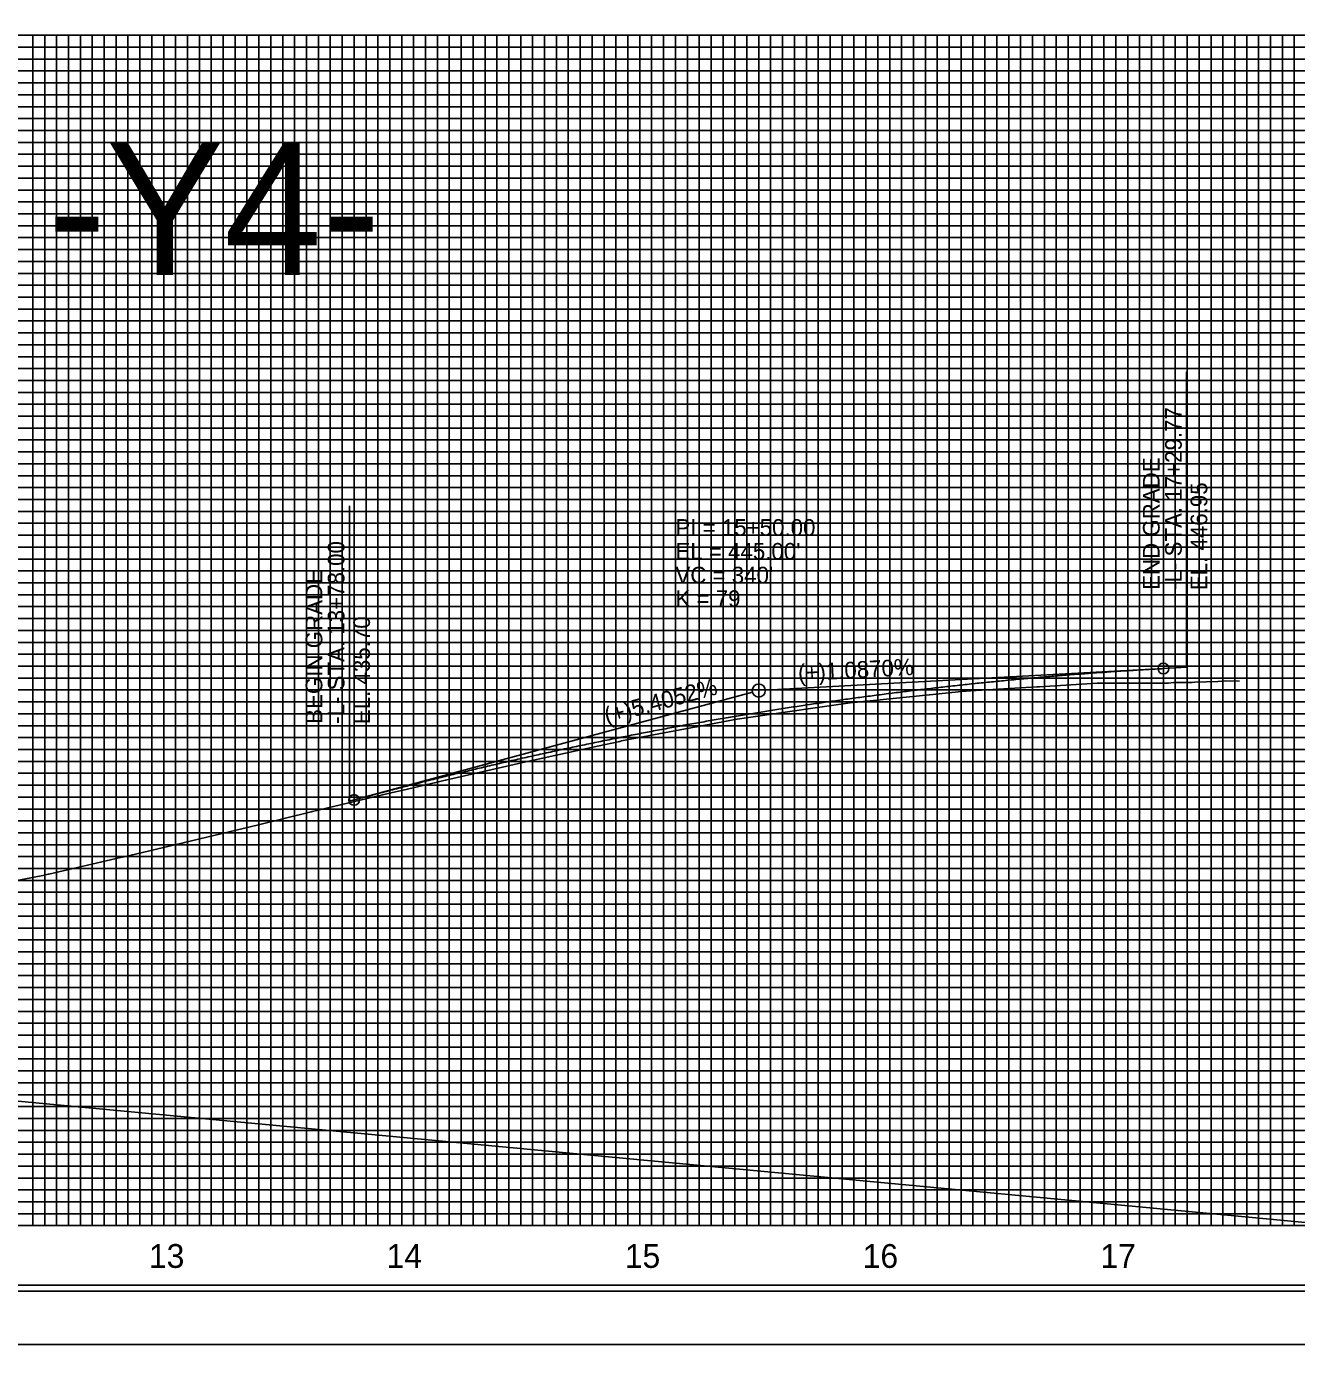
# Model space of a CAD drawing. Extents: x 571503 to 593215, y -77195 to -51828.
# Drawn here: x 586818 to 587352, y -53731 to -53168 of the extents above; entities that cross this region are included whole.
import ezdxf

# ---------------------------------------------------------------- set-up
doc = ezdxf.new("R2010")
doc.units = 0
for name, color, linetype in [('Default', 7, 'Continuous'), ('Exist Vertical Profile Ground Line', 7, 'Continuous'), ('Exist Vertical Profile Horizontal Axis Label Major', 7, 'Continuous'), ('Prop PFL Text', 7, 'Continuous'), ('Prop Vertical Profile Curve Label', 7, 'Continuous'), ('Prop Vertical Profile Grade', 7, 'Continuous'), ('Prop Vertical Profile Grade Label', 7, 'Continuous'), ('Prop VPI Label', 7, 'Continuous'), ('Sheet Clip Boundary CELL', 7, 'Continuous'), ('Sheet DOT Grid CELL', 7, 'Continuous'), ('Sheet Plot Border Inside CELL', 7, 'Continuous'), ('Sheet Plot Border Outside CELL', 7, 'Continuous'), ('Sheet Profile CELL', 7, 'Continuous'), ('Sheet Profile Grid Major CELL', 7, 'Continuous'), ('Sheet Profile Grid Middle CELL', 7, 'Continuous'), ('Sheet Profile Grid Minor CELL', 7, 'Continuous')]:
    doc.layers.add(name, color=color, linetype=linetype)

msp = doc.modelspace()

# ---------------------------------------------------------------- linework, layer by layer
at = {"layer": 'Exist Vertical Profile Ground Line'}
msp.add_lwpolyline([(586805.4, -53527.81), (586825.12, -53523.99), (586827.43, -53523.54), (586827.74, -53523.47), (586857.78, -53516.5), (586859.3, -53516.15), (586883.55, -53510.52), (586883.76, -53510.47), (586884.7, -53510.25), (586915.74, -53502.7), (586937.93, -53497.31), (586938.31, -53497.22), (586938.45, -53497.19), (586970.17, -53489.65), (586970.24, -53489.64), (586978.3, -53487.72), (586990.78, -53484.78), (586994.25, -53483.98), (586994.39, -53483.95), (587026.19, -53476.68), (587026.79, -53476.55), (587058.13, -53469.76), (587058.17, -53469.75), (587067.52, -53467.72), (587068.24, -53467.55), (587099.6, -53461.65), (587099.81, -53461.62), (587116.66, -53458.44), (587116.9, -53458.4), (587148.58, -53453.83), (587148.7, -53453.81), (587165.35, -53451.41), (587165.91, -53451.33), (587197.5, -53448.14), (587197.66, -53448.12), (587211.08, -53446.77), (587211.25, -53446.75), (587215.05, -53446.5), (587242.81, -53444.87), (587242.83, -53444.87), (587243.88, -53444.75), (587268.09, -53443.28), (587269, -53443.25), (587298.02, -53443.2), (587300.11, -53443.05), (587305.77, -53442.93), (587306.85, -53442.92), (587306.97, -53442.98), (587308.03, -53442.94), (587308.97, -53442.9), (587318.8, -53442.57), (587322.21, -53442.33), (587327.89, -53442.44)], dxfattribs=at)
at = {"layer": 'Prop PFL Text'}
msp.add_line((571620.66, -52186.29), (592499.52, -54154.87), dxfattribs=at)
at = {"layer": 'Prop Vertical Profile Curve Label'}
for centre in [(587295.93, -53437.13), (586955.93, -53492.32)]:
    msp.add_circle(centre, 2.25, dxfattribs=at)
at = {"layer": 'Prop Vertical Profile Grade'}
for p, q in [((587295.93, -53437.13), (587305.7, -53436.6)), ((586953.93, -53492.86), (586955.93, -53492.32))]:
    msp.add_line(p, q, dxfattribs=at)
msp.add_spline([(586955.93, -53492.32), (586962.73, -53490.49), (586969.53, -53488.7), (586976.33, -53486.94), (586983.13, -53485.2), (586989.93, -53483.5), (586996.73, -53481.82), (587003.53, -53480.17), (587010.33, -53478.56), (587017.13, -53476.97), (587023.93, -53475.41), (587030.73, -53473.88), (587037.53, -53472.38), (587044.33, -53470.91), (587051.13, -53469.47), (587057.93, -53468.05), (587064.73, -53466.67), (587071.53, -53465.32), (587078.33, -53463.99), (587085.13, -53462.7), (587091.93, -53461.44), (587098.73, -53460.2), (587105.53, -53458.99), (587112.33, -53457.82), (587119.13, -53456.67), (587125.93, -53455.55), (587132.73, -53454.46), (587139.53, -53453.4), (587146.33, -53452.37), (587153.13, -53451.37), (587159.93, -53450.4), (587166.73, -53449.46), (587173.53, -53448.54), (587180.33, -53447.66), (587187.13, -53446.81), (587193.93, -53445.98), (587200.73, -53445.19), (587207.53, -53444.42), (587214.33, -53443.68), (587221.13, -53442.98), (587227.93, -53442.3), (587234.73, -53441.65), (587241.53, -53441.03), (587248.33, -53440.44), (587255.13, -53439.88), (587261.93, -53439.35), (587268.73, -53438.85), (587275.53, -53438.37), (587282.33, -53437.93), (587289.13, -53437.52), (587295.93, -53437.13)], degree=3, dxfattribs=at)
at = {"layer": 'Prop VPI Label'}
for p, q in [((587305.7, -53436.6), (587305.7, -53312.47)), ((586953.93, -53492.86), (586953.93, -53368.73)), ((587295.93, -53437.13), (587128.68, -53446.22)), ((586955.93, -53492.32), (587123.28, -53447.09))]:
    msp.add_line(p, q, dxfattribs=at)
msp.add_circle((587125.93, -53446.37), 2.75, dxfattribs=at)
at = {"layer": 'Sheet Clip Boundary CELL'}
msp.add_lwpolyline([(585975.93, -53171.12), (587375.93, -53171.12), (587375.93, -53671.12), (585975.93, -53671.12)], close=True, dxfattribs=at)
at = {"layer": 'Sheet DOT Grid CELL'}
for p, q in [((585925.93, -53171.12), (587425.82, -53171.12)), ((586825.93, -53671.12), (586825.93, -53171.12)), ((586825.93, -53171.12), (586825.93, -53671.12)), ((586875.93, -53671.12), (586875.93, -53171.12)), ((586875.93, -53171.12), (586875.93, -53671.12)), ((586925.93, -53671.12), (586925.93, -53171.12)), ((586925.93, -53171.12), (586925.93, -53671.12)), ((586975.93, -53671.12), (586975.93, -53171.12)), ((586975.93, -53171.12), (586975.93, -53671.12)), ((587025.93, -53671.12), (587025.93, -53171.12)), ((587025.93, -53171.12), (587025.93, -53671.12)), ((587075.93, -53671.12), (587075.93, -53171.12)), ((587075.93, -53171.12), (587075.93, -53671.12)), ((587125.93, -53671.12), (587125.93, -53171.12)), ((587125.93, -53171.12), (587125.93, -53671.12)), ((587175.93, -53671.12), (587175.93, -53171.12)), ((587175.93, -53171.12), (587175.93, -53671.12)), ((587225.93, -53671.12), (587225.93, -53171.12)), ((587225.93, -53171.12), (587225.93, -53671.12)), ((587275.93, -53671.12), (587275.93, -53171.12)), ((587275.93, -53171.12), (587275.93, -53671.12)), ((587325.93, -53671.12), (587325.93, -53171.12)), ((587325.93, -53171.12), (587325.93, -53671.12)), ((585925.93, -53221.12), (587425.93, -53221.12)), ((585925.93, -53221.12), (587425.82, -53221.12)), ((585925.93, -53271.12), (587425.93, -53271.12)), ((585925.93, -53271.12), (587425.82, -53271.12)), ((585925.93, -53321.12), (587425.93, -53321.12)), ((585925.93, -53321.12), (587425.82, -53321.12)), ((585925.93, -53371.12), (587425.93, -53371.12)), ((585925.93, -53371.12), (587425.82, -53371.12)), ((585925.93, -53421.12), (587425.93, -53421.12)), ((585925.93, -53421.12), (587425.82, -53421.12)), ((585925.93, -53471.12), (587425.93, -53471.12)), ((585925.93, -53471.12), (587425.82, -53471.12)), ((585925.93, -53521.12), (587425.82, -53521.12)), ((585925.93, -53571.12), (587425.82, -53571.12)), ((586575.93, -53571.12), (587425.93, -53571.12)), ((585925.93, -53621.12), (587425.93, -53621.12)), ((585925.93, -53621.12), (587425.82, -53621.12))]:
    msp.add_line(p, q, dxfattribs=at)
at = {"layer": 'Sheet Plot Border Inside CELL'}
msp.add_lwpolyline([(585771.93, -53698.67), (587438.43, -53698.67), (587438.43, -52643.57), (585771.93, -52643.57)], close=True, dxfattribs=at)
at = {"layer": 'Sheet Plot Border Outside CELL'}
msp.add_lwpolyline([(585758.93, -53721.12), (587442.93, -53721.12), (587442.93, -52621.12), (585758.93, -52621.12)], close=True, dxfattribs=at)
at = {"layer": 'Sheet Profile CELL'}
for p, q in [((585925.93, -53171.12), (587425.93, -53171.12)), ((587425.93, -53671.12), (585925.93, -53671.12)), ((585925.93, -53696.12), (587425.93, -53696.12)), ((585758.93, -53721.12), (587442.93, -53721.12))]:
    msp.add_line(p, q, dxfattribs=at)
msp.add_lwpolyline([(587425.93, -52646.12), (585925.93, -52646.12), (585925.93, -53696.12), (587425.93, -53696.12)], close=True, dxfattribs=at)
at = {"layer": 'Sheet Profile Grid Major CELL'}
for p, q in [((586825.93, -53171.12), (586875.93, -53171.12)), ((586925.93, -53171.12), (586975.93, -53171.12)), ((587025.93, -53171.12), (587075.93, -53171.12)), ((587125.93, -53171.12), (587175.93, -53171.12)), ((587225.93, -53171.12), (587275.93, -53171.12)), ((587325.93, -53171.12), (587375.93, -53171.12)), ((587325.93, -53671.12), (587325.93, -53671.12))]:
    msp.add_line(p, q, dxfattribs=at)
for points in [[(586775.93, -53671.12), (586825.93, -53671.12), (586825.93, -53171.12), (586875.93, -53171.12), (586875.93, -53671.12), (586925.93, -53671.12), (586925.93, -53171.12), (586975.93, -53171.12), (586975.93, -53671.12), (587025.93, -53671.12), (587025.93, -53171.12), (587075.93, -53171.12), (587075.93, -53671.12), (587125.93, -53671.12), (587125.93, -53171.12), (587175.93, -53171.12), (587175.93, -53671.12), (587225.93, -53671.12), (587225.93, -53171.12), (587275.93, -53171.12), (587275.93, -53671.12), (587325.93, -53671.12), (587325.93, -53671.12), (587325.93, -53171.12), (587375.93, -53171.12)], [(587425.93, -53221.12), (585925.93, -53221.12)], [(587425.93, -53271.12), (585925.93, -53271.12), (585925.93, -53321.12), (587425.93, -53321.12)], [(587425.93, -53371.12), (585925.93, -53371.12), (585925.93, -53421.12), (587425.93, -53421.12)], [(587425.93, -53471.12), (585925.93, -53471.12), (585925.93, -53521.12), (587425.93, -53521.12)], [(587425.93, -53571.12), (585925.93, -53571.12), (585925.93, -53571.12), (585925.93, -53621.12), (587425.93, -53621.12)], [(587425.93, -53671.12), (585925.93, -53671.12)]]:
    msp.add_lwpolyline(points, dxfattribs=at)
at = {"layer": 'Sheet Profile Grid Middle CELL'}
for p, q in [((586850.93, -53671.12), (586850.93, -53171.12)), ((586850.93, -53171.12), (586900.93, -53171.12)), ((586900.93, -53171.12), (586900.93, -53671.12)), ((586950.93, -53671.12), (586950.93, -53171.12)), ((586950.93, -53171.12), (587000.93, -53171.12)), ((587000.93, -53171.12), (587000.93, -53671.12)), ((587050.93, -53671.12), (587050.93, -53171.12)), ((587050.93, -53171.12), (587100.93, -53171.12)), ((587100.93, -53171.12), (587100.93, -53671.12)), ((587150.93, -53671.12), (587150.93, -53171.12)), ((587150.93, -53171.12), (587200.93, -53171.12)), ((587200.93, -53171.12), (587200.93, -53671.12)), ((587250.93, -53671.12), (587250.93, -53171.12)), ((587250.93, -53171.12), (587300.93, -53171.12)), ((587300.93, -53171.12), (587300.93, -53671.12)), ((587350.93, -53671.12), (587350.93, -53171.12)), ((586800.93, -53671.12), (586850.93, -53671.12)), ((586900.93, -53671.12), (586950.93, -53671.12)), ((587000.93, -53671.12), (587050.93, -53671.12)), ((587100.93, -53671.12), (587150.93, -53671.12)), ((587200.93, -53671.12), (587250.93, -53671.12)), ((587300.93, -53671.12), (587350.93, -53671.12))]:
    msp.add_line(p, q, dxfattribs=at)
for points in [[(585925.93, -53196.12), (587425.93, -53196.12)], [(587375.93, -53246.12), (585925.93, -53246.12), (585925.93, -53296.12), (587425.93, -53296.12)], [(587425.93, -53346.12), (585925.93, -53346.12), (585925.93, -53396.12), (587425.93, -53396.12)], [(587425.93, -53446.12), (585925.93, -53446.12), (585925.93, -53496.12), (587425.93, -53496.12)], [(587425.93, -53546.12), (585925.93, -53546.12), (585925.93, -53596.12), (587425.93, -53596.12)], [(587425.93, -53646.12), (585925.93, -53646.12)]]:
    msp.add_lwpolyline(points, dxfattribs=at)
at = {"layer": 'Sheet Profile Grid Minor CELL'}
for p, q in [((586575.93, -53176.12), (587375.93, -53176.12)), ((587375.93, -53181.12), (586575.93, -53181.12)), ((586575.93, -53186.12), (587375.93, -53186.12)), ((587375.93, -53191.12), (586575.93, -53191.12)), ((586575.93, -53201.12), (587375.93, -53201.12)), ((587375.93, -53206.12), (586575.93, -53206.12)), ((586575.93, -53211.12), (587375.93, -53211.12)), ((587375.93, -53216.12), (586575.93, -53216.12)), ((586575.93, -53226.12), (587375.93, -53226.12)), ((587375.93, -53231.12), (586575.93, -53231.12)), ((586575.93, -53236.12), (587375.93, -53236.12)), ((587375.93, -53241.12), (586575.93, -53241.12)), ((586575.93, -53251.12), (587375.93, -53251.12)), ((587375.93, -53256.12), (586575.93, -53256.12)), ((586575.93, -53261.12), (587375.93, -53261.12)), ((587375.93, -53266.12), (586575.93, -53266.12)), ((586575.93, -53276.12), (587375.93, -53276.12)), ((587375.93, -53281.12), (586575.93, -53281.12)), ((586575.93, -53286.12), (587375.93, -53286.12)), ((587375.93, -53291.12), (586575.93, -53291.12)), ((586575.93, -53301.12), (587375.93, -53301.12)), ((587375.93, -53306.12), (586575.93, -53306.12)), ((586575.93, -53311.12), (587375.93, -53311.12)), ((587375.93, -53316.12), (586575.93, -53316.12)), ((586575.93, -53326.12), (587375.93, -53326.12)), ((587375.93, -53331.12), (586575.93, -53331.12)), ((586575.93, -53336.12), (587375.93, -53336.12)), ((587375.93, -53341.12), (586575.93, -53341.12)), ((586575.93, -53351.12), (587375.93, -53351.12)), ((587375.93, -53356.12), (586575.93, -53356.12)), ((586575.93, -53361.12), (587375.93, -53361.12)), ((587375.93, -53366.12), (586575.93, -53366.04)), ((586575.93, -53376.12), (587375.93, -53376.12)), ((587375.93, -53381.12), (586575.93, -53381.12)), ((586575.93, -53386.12), (587375.93, -53386.12)), ((587375.93, -53391.12), (586575.93, -53391.12)), ((586575.93, -53401.12), (587375.93, -53401.12)), ((587375.93, -53406.12), (586575.93, -53406.12)), ((586575.93, -53411.12), (587375.93, -53411.12)), ((587375.93, -53416.12), (586575.93, -53416.12)), ((586575.93, -53426.12), (587375.93, -53426.12)), ((587375.93, -53431.12), (586575.93, -53431.12)), ((586575.93, -53436.12), (587375.93, -53436.12)), ((587375.93, -53441.12), (586575.93, -53441.12)), ((586575.93, -53451.12), (587375.93, -53451.12)), ((587375.93, -53456.12), (586575.93, -53456.12)), ((586575.93, -53461.12), (587375.93, -53461.12)), ((587375.93, -53466.12), (586575.93, -53466.12)), ((586575.93, -53476.12), (587375.93, -53476.12)), ((587375.93, -53481.12), (586575.93, -53481.12)), ((586575.93, -53486.12), (587375.93, -53486.12)), ((587375.93, -53491.12), (586575.93, -53491.12)), ((586575.93, -53501.12), (587375.93, -53501.12)), ((587375.93, -53506.12), (586575.93, -53506.12)), ((586575.93, -53511.12), (587375.93, -53511.12)), ((587375.93, -53516.12), (586575.93, -53516.12)), ((586575.93, -53526.12), (587375.93, -53526.12)), ((587375.93, -53531.12), (586575.93, -53531.12)), ((586575.93, -53536.12), (587375.93, -53536.12)), ((587375.93, -53541.12), (586575.93, -53541.12)), ((586575.93, -53551.12), (587375.93, -53551.12)), ((587375.93, -53556.12), (586575.93, -53556.12)), ((586575.93, -53561.12), (587375.93, -53561.12)), ((587375.93, -53566.12), (586575.93, -53566.12)), ((586575.93, -53576.12), (587375.93, -53576.12)), ((587375.93, -53581.12), (586575.93, -53581.12)), ((586575.93, -53586.12), (587375.93, -53586.12)), ((587375.93, -53591.12), (586575.93, -53591.12)), ((586575.93, -53601.12), (587375.93, -53601.12)), ((587375.93, -53606.12), (586575.93, -53606.12)), ((586575.93, -53611.12), (587375.93, -53611.12)), ((587375.93, -53616.12), (586575.93, -53616.12)), ((586575.93, -53626.12), (587375.93, -53626.12)), ((587375.93, -53631.12), (586575.93, -53631.12)), ((586575.93, -53636.12), (587375.93, -53636.12)), ((587375.93, -53641.12), (586575.93, -53641.12)), ((586575.93, -53651.12), (587375.93, -53651.12)), ((587375.93, -53656.12), (586575.93, -53656.12)), ((586575.93, -53661.12), (587375.93, -53661.12)), ((586575.93, -53666.12), (587375.93, -53666.12))]:
    msp.add_line(p, q, dxfattribs=at)
for points in [[(586815.93, -53671.12), (586820.93, -53671.12), (586820.93, -53171.12), (586830.93, -53171.12), (586830.93, -53671.12), (586835.93, -53671.12), (586835.93, -53171.12), (586840.93, -53171.12), (586840.93, -53671.12), (586845.93, -53671.12), (586845.93, -53171.12), (586855.93, -53171.12), (586855.93, -53671.12), (586860.93, -53671.12), (586860.93, -53171.12), (586865.93, -53171.12), (586865.93, -53671.12), (586870.93, -53671.12), (586870.93, -53171.12), (586880.93, -53171.12), (586880.93, -53671.12), (586885.93, -53671.12), (586885.93, -53171.12), (586890.93, -53171.12), (586890.93, -53671.12), (586895.93, -53671.12), (586895.93, -53171.12), (586905.93, -53171.12), (586905.93, -53671.12), (586910.93, -53671.12), (586910.93, -53171.12), (586915.93, -53171.12), (586915.93, -53671.12), (586920.93, -53671.12), (586920.93, -53171.12), (586930.93, -53171.12), (586930.93, -53671.12), (586935.93, -53671.12), (586935.93, -53171.12), (586940.93, -53171.12), (586940.93, -53671.12), (586945.93, -53671.12), (586945.93, -53171.12), (586955.93, -53171.12), (586955.93, -53671.12), (586960.93, -53671.12), (586960.93, -53171.12), (586965.93, -53171.12), (586965.93, -53671.12), (586970.93, -53671.12), (586970.93, -53171.12), (586980.93, -53171.12), (586980.93, -53671.12), (586985.93, -53671.12), (586985.93, -53171.12), (586990.93, -53171.12), (586990.93, -53671.12), (586995.93, -53671.12), (586995.93, -53171.12), (587005.93, -53171.12), (587005.93, -53671.12), (587010.93, -53671.12), (587010.93, -53171.12), (587015.93, -53171.12), (587015.93, -53671.12), (587020.93, -53671.12), (587020.93, -53171.12), (587030.93, -53171.12), (587030.93, -53671.12), (587035.93, -53671.12), (587035.93, -53171.12), (587040.93, -53171.12), (587040.93, -53671.12), (587045.93, -53671.12), (587045.93, -53171.12), (587055.93, -53171.12), (587055.93, -53671.12), (587060.93, -53671.12), (587060.93, -53171.12), (587065.93, -53171.12), (587065.93, -53671.12), (587070.93, -53671.12), (587070.93, -53171.12), (587080.93, -53171.12), (587080.93, -53671.12), (587085.93, -53671.12), (587085.93, -53171.12), (587090.93, -53171.12), (587090.93, -53671.12), (587095.93, -53671.12), (587095.93, -53171.12), (587105.93, -53171.12), (587105.93, -53671.12), (587110.93, -53671.12), (587110.93, -53171.12), (587115.93, -53171.12), (587115.93, -53671.12)], [(587115.93, -53671.12), (587120.93, -53671.12), (587120.93, -53171.12), (587130.93, -53171.12), (587130.93, -53671.12), (587135.93, -53671.12), (587135.93, -53171.12), (587140.93, -53171.12), (587140.93, -53671.12), (587145.93, -53671.12), (587145.93, -53171.12), (587155.93, -53171.12), (587155.93, -53671.12), (587160.93, -53671.12), (587160.93, -53171.12), (587165.93, -53171.12), (587165.93, -53671.12), (587170.93, -53671.12), (587170.93, -53171.12), (587180.93, -53171.12), (587180.93, -53671.12), (587185.93, -53671.12), (587185.93, -53171.12), (587190.93, -53171.12), (587190.93, -53671.12), (587195.93, -53671.12), (587195.93, -53171.12), (587205.93, -53171.12), (587205.93, -53671.12), (587210.93, -53671.12), (587210.93, -53171.12), (587215.93, -53171.12), (587215.93, -53671.12), (587220.93, -53671.12), (587220.93, -53171.12), (587230.93, -53171.12), (587230.93, -53671.12), (587235.93, -53671.12), (587235.93, -53171.12), (587240.93, -53171.12), (587240.93, -53671.12), (587245.93, -53671.12), (587245.93, -53171.12), (587255.93, -53171.12), (587255.93, -53671.12), (587260.93, -53671.12), (587260.93, -53171.12), (587265.93, -53171.12), (587265.93, -53671.12), (587270.93, -53671.12), (587270.93, -53171.12), (587280.93, -53171.12), (587280.93, -53671.12), (587285.93, -53671.12), (587285.93, -53171.12), (587290.93, -53171.12), (587290.93, -53671.12), (587295.93, -53671.12), (587295.93, -53171.12), (587305.93, -53171.12), (587305.93, -53671.12), (587310.93, -53671.12), (587310.93, -53171.12), (587315.93, -53171.12), (587315.93, -53671.12), (587320.93, -53671.12), (587320.93, -53171.12), (587330.93, -53171.12), (587330.93, -53671.12), (587335.93, -53671.12), (587335.93, -53171.12), (587340.93, -53171.12), (587340.93, -53671.12), (587345.93, -53671.12), (587345.93, -53171.12), (587355.93, -53171.12)]]:
    msp.add_lwpolyline(points, dxfattribs=at)

# ---------------------------------------------------------------- texts
at = {"layer": 'Default'}
msp.add_text('-Y4-', height=55.361, dxfattribs=at).set_placement((586827.16, -53271.83))
at = {"layer": 'Exist Vertical Profile Horizontal Axis Label Major'}
for s, p in [('13', (586869.74, -53688.87)), ('14', (586969.58, -53688.87)), ('15', (587069.67, -53688.87)), ('16', (587169.61, -53688.87)), ('17', (587269.47, -53688.87))]:
    msp.add_text(s, height=10, dxfattribs=at).set_placement(p)
at = {"layer": 'Prop Vertical Profile Curve Label'}
for s, p in [("VC = 340'", (587090.93, -53401.37)), ('K = 79', (587090.93, -53411.24))]:
    msp.add_text(s, height=7, dxfattribs=at).set_placement(p)
at = {"layer": 'Prop Vertical Profile Grade Label'}
for s, rotation, p in [('(+)1.0870%', 3.111, (587142.6, -53442.46)), ('(+)5.4052%', 15.1235, (587062.12, -53460.51))]:
    msp.add_text(s, height=7, rotation=rotation, dxfattribs=at).set_placement(p)
at = {"layer": 'Prop VPI Label'}
for s, p in [('-L- STA. 17+29.77', (587303.64, -53404.08)), ('END GRADE', (587294.34, -53404.08)), ('EL. 446.95', (587314.37, -53404.21)), ('-L- STA. 13+78.00', (586951.87, -53460.34)), ('BEGIN GRADE', (586942.57, -53460.34)), ('EL. 435.70', (586962.6, -53460.47))]:
    msp.add_text(s, height=7, rotation=90, dxfattribs=at).set_placement(p)
for s, p in [('PI = 15+50.00', (587090.93, -53381.37)), ("EL = 445.00'", (587090.93, -53391.37))]:
    msp.add_text(s, height=7, dxfattribs=at).set_placement(p)

doc.saveas('drawing.dxf')
